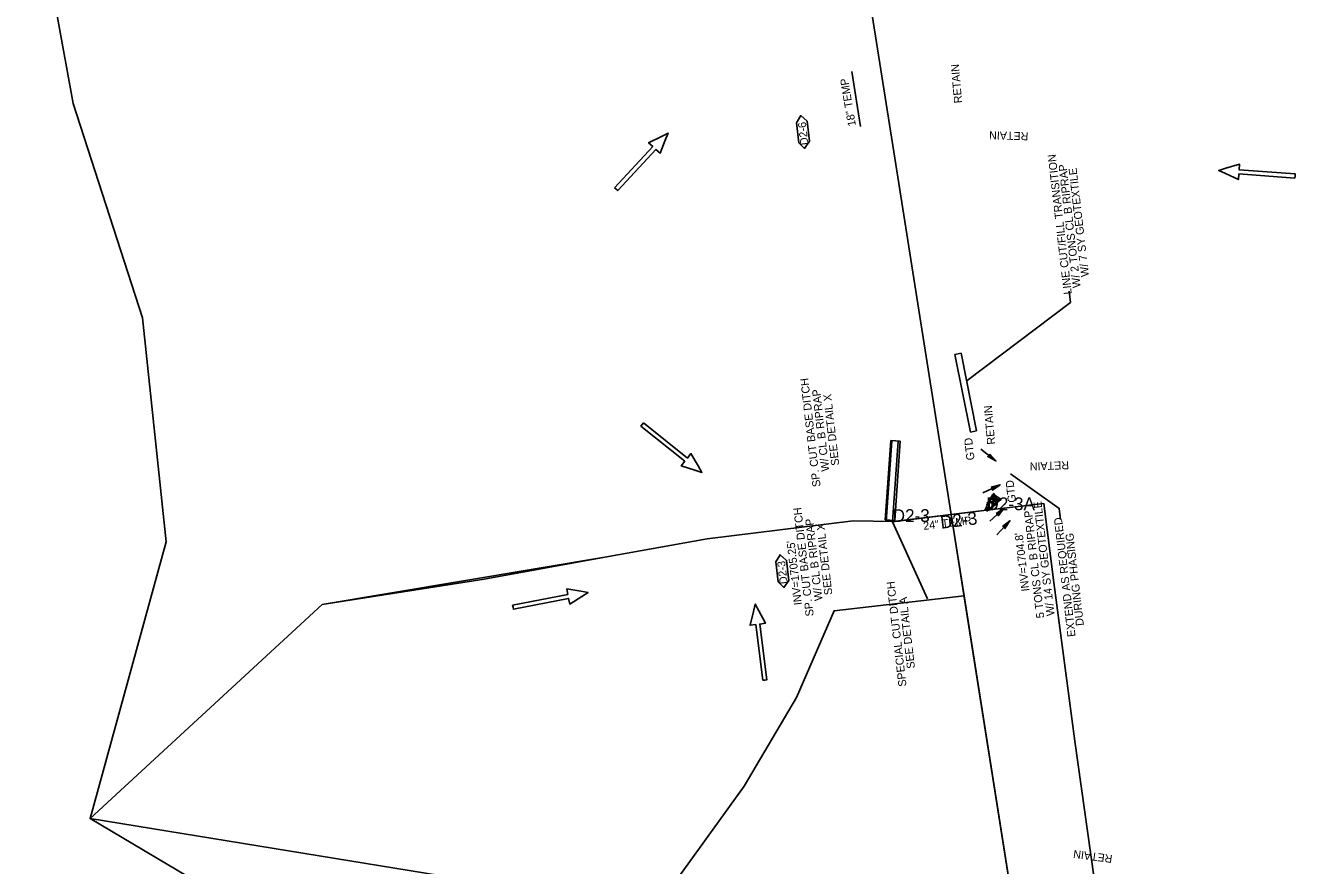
# Model space of a CAD drawing. Extents: x 465700 to 483515, y 488970 to 507540.
# Drawn here: x 477666 to 478460, y 495749 to 496274 of the extents above; entities that cross this region are included whole.
import ezdxf

# ---------------------------------------------------------------- set-up
doc = ezdxf.new("R2010")
doc.units = 0
for name, color, linetype in [('Default', 7, 'Continuous'), ('Exist Plan Preparation Drainage Flow Arrows', 7, 'Continuous'), ('Exist Plan Preparation Watershed Blue', 7, 'Continuous'), ('Prop Drainage Structure Box Number Symbol CELL', 7, 'Continuous'), ('Prop Drainage Structure Pipe Collar Label', 7, 'Continuous'), ('Prop Drainage Structure Pipe RCP 24in Class IV', 7, 'Continuous'), ('Prop Drainage Structure Pipe RCP 24in Class IV Label', 7, 'Continuous'), ('Prop Drainage Structure Pipe Side Drain 18in', 7, 'Continuous'), ('Prop Drainage Structure Pipe Side Drain 18in Label', 7, 'Continuous'), ('Prop Drainage Structure Pipe Stub Out CELL', 7, 'Continuous'), ('Prop Drainage Structure Tops and Inverts LABEL', 7, 'Continuous'), ('Prop Earthen Structure Ditch Flow Line', 7, 'Continuous'), ('Prop Earthen Structure V Ditch Lateral Detail Label', 7, 'Continuous'), ('Prop Erosion Rip Rap Class B', 7, 'Continuous'), ('Prop Erosion Rip Rap Pad at Outlet CELL', 7, 'Continuous'), ('Prop Erosion Rip Rap Pad at Outlet Label', 7, 'Continuous'), ('Prop Plan Preparation Grade to Drain Arrows CELL', 7, 'Continuous'), ('Prop Plan Preparation Grade to Drain Arrows Label', 7, 'Continuous'), ('Scratch_Level_4', 7, 'Continuous'), ('Scratch_Level_8', 7, 'Continuous')]:
    doc.layers.add(name, color=color, linetype=linetype)

# ---------------------------------------------------------------- blocks, each defined once
blk = doc.blocks.new('Existing ground flow arrow')
at = {"layer": 'Default'}
blk.add_line((2.5, -4.33), (2.5, -4.33), dxfattribs=at)
blk.add_lwpolyline([(-1.29, -47.2), (-1.28, -12.53), (-4.77, -12.53), (-1.65, -4.33), (0, 0), (1.65, -4.33), (4.78, -12.53), (1.28, -12.52), (1.29, -47.19), (0, -47.2)], close=True, dxfattribs=at)

msp = doc.modelspace()

# ---------------------------------------------------------------- linework, layer by layer
at = {"layer": 'Exist Plan Preparation Watershed Blue'}
for points in [[(478193.03, 496293.65), (478208.66, 496194.88), (478224.29, 496096.11), (478244.5, 495968.4), (478252.55, 495917.62), (478171.36, 495908.37), (478147.78, 495854.29), (478115.21, 495798.76), (478059.1, 495721.12), (477706.62, 495778.57), (477754.11, 495951.45), (477739.34, 496091.29), (477696.06, 496225.09), (477666.24, 496388.81)], [(478286.82, 495701.03), (478271.18, 495799.8), (478255.55, 495898.57), (478244.5, 495968.4), (478264.82, 495970.97), (478302.44, 495975.33), (478308.68, 495926.08), (478321.83, 495826.95), (478335.71, 495727.91)], [(478059.1, 495721.12), (478115.21, 495798.76), (478147.78, 495854.29), (478171.36, 495908.37), (478252.55, 495917.62), (478301.78, 495606.48)], [(478018.35, 495593.67), (477706.62, 495778.57), (478059.1, 495721.12)]]:
    msp.add_lwpolyline(points, dxfattribs=at)
at = {"layer": 'Prop Drainage Structure Box Number Symbol CELL'}
for points in [[(478149.28, 496200.57), (478147.83, 496213.09), (478150.56, 496217.54), (478154.57, 496214.03), (478156.02, 496201.51), (478152.93, 496197.13), (478149.28, 496200.57)], [(478136.34, 495926.37), (478134.89, 495938.89), (478137.63, 495943.34), (478141.64, 495939.83), (478143.09, 495927.31), (478139.99, 495922.93), (478136.34, 495926.37)]]:
    msp.add_lwpolyline(points, dxfattribs=at)
at = {"layer": 'Prop Drainage Structure Pipe RCP 24in Class IV'}
msp.add_line((478208.45, 495964.09), (478266.49, 495971.16), dxfattribs=at)
at = {"layer": 'Prop Drainage Structure Pipe Side Drain 18in'}
msp.add_line((478187.9, 496210.87), (478182.45, 496245.11), dxfattribs=at)
at = {"layer": 'Prop Drainage Structure Pipe Stub Out CELL'}
msp.add_line((478207.93, 495963.82), (478207.93, 495963.82), dxfattribs=at)
msp.add_line((478207.93, 495963.82), (478207.93, 495963.82), dxfattribs=at)
msp.add_lwpolyline([(478207.93, 495963.84), (478207.95, 495963.83), (478207.94, 495963.81), (478207.92, 495963.82), (478207.93, 495963.84)], dxfattribs=at)
at = {"layer": 'Prop Earthen Structure Ditch Flow Line'}
msp.add_line((478207.32, 496014.49), (478203.94, 495964.11), dxfattribs=at)
for points in [[(478211.31, 496014.22), (478207.93, 495963.85)], [(478229.76, 495915.9), (478207.93, 495963.85)]]:
    msp.add_lwpolyline(points, dxfattribs=at)
at = {"layer": 'Prop Erosion Rip Rap Class B'}
for p, q in [((478250.75, 496069.23), (478246.82, 496068.45)), ((478246.82, 496068.45), (478256.49, 496019.98)), ((478260.41, 496020.76), (478250.75, 496069.23)), ((478256.49, 496019.98), (478260.41, 496020.76)), ((478206.71, 496014.71), (478203.24, 495965.13)), ((478212.69, 496014.29), (478206.71, 496014.71)), ((478209.23, 495964.71), (478212.69, 496014.29)), ((478203.24, 495965.13), (478209.23, 495964.71))]:
    msp.add_line(p, q, dxfattribs=at)
at = {"layer": 'Prop Erosion Rip Rap Pad at Outlet CELL'}
msp.add_line((478266.49, 495971.16), (478266.49, 495971.16), dxfattribs=at)
msp.add_line((478266.49, 495971.16), (478266.49, 495971.16), dxfattribs=at)
for points in [[(478269.53, 495979.7), (478269.87, 495979.73), (478270.28, 495979.54), (478270.4, 495979.24), (478270.23, 495978.99), (478269.7, 495979.27), (478269.49, 495979.5), (478269.53, 495979.7)], [(478270.6, 495979.83), (478270.29, 495979.92), (478270.02, 495980.24), (478270.06, 495980.63), (478270.26, 495980.71), (478270.76, 495980.37), (478270.71, 495979.99), (478270.6, 495979.83)], [(478270.66, 495979.28), (478270.64, 495979.79), (478270.95, 495980.77), (478271.65, 495980.92), (478272.01, 495980.52), (478271.59, 495979.36), (478271.17, 495979.11), (478270.62, 495979.22)], [(478271.23, 495981.53), (478271.32, 495981.24), (478271.12, 495980.78), (478270.81, 495980.72), (478270.68, 495980.86), (478270.83, 495981.43), (478271, 495981.54), (478271.23, 495981.53)], [(478272.86, 495979.12), (478272.52, 495979.27), (478272, 495979.63), (478272.14, 495980.18), (478272.37, 495980.37), (478273.07, 495979.75), (478273.09, 495979.37), (478272.86, 495979.12)], [(478265.76, 495971.87), (478265.99, 495971.81), (478266.56, 495971.69), (478266.5, 495971.36), (478266.4, 495971.2), (478265.8, 495971.33), (478265.59, 495971.62), (478265.76, 495971.87)], [(478266.96, 495972.99), (478266.93, 495972.64), (478266.78, 495972.03), (478266.26, 495971.88), (478265.93, 495972.11), (478266.28, 495972.96), (478266.61, 495973.09), (478266.96, 495972.99)], [(478267.93, 495972.5), (478267.46, 495972.69), (478266.63, 495973.26), (478266.73, 495974.02), (478267.13, 495974.25), (478268.1, 495973.48), (478268.19, 495972.9), (478267.93, 495972.5)], [(478267.38, 495975.22), (478267.47, 495974.94), (478267.28, 495974.48), (478266.97, 495974.41), (478266.84, 495974.55), (478267.01, 495975.12), (478267.17, 495975.24), (478267.38, 495975.22)], [(478268.43, 495971.06), (478267.99, 495971.14), (478267.01, 495971.45), (478266.86, 495972.15), (478267.2, 495972.57), (478268.35, 495972.12), (478268.65, 495971.55), (478268.5, 495971.16)], [(478267.93, 495975.03), (478267.53, 495975.16), (478267.04, 495975.5), (478267.14, 495976.06), (478267.45, 495976.22), (478268.1, 495975.65), (478268.09, 495975.26), (478267.93, 495975.03)], [(478267.93, 495974.99), (478267.98, 495974.68), (478267.76, 495974.25), (478267.48, 495974.16), (478267.3, 495974.29), (478267.51, 495974.92), (478267.71, 495975.01), (478267.93, 495974.99)], [(478268.22, 495974.47), (478268.3, 495974.2), (478268.1, 495973.74), (478267.8, 495973.66), (478267.67, 495973.8), (478267.83, 495974.38), (478268, 495974.49), (478268.22, 495974.47)], [(478268.22, 495976.93), (478268.3, 495976.64), (478268.1, 495976.18), (478267.81, 495976.12), (478267.68, 495976.26), (478267.83, 495976.83), (478268, 495976.93), (478268.22, 495976.93)], [(478267.97, 495977.45), (478268.23, 495977.49), (478268.64, 495977.35), (478268.77, 495977.02), (478268.59, 495976.75), (478268.06, 495977.03), (478267.87, 495977.29), (478267.97, 495977.45)], [(478268.67, 495971.99), (478268.48, 495972.12), (478268.11, 495972.37), (478268.19, 495972.69), (478268.3, 495972.84), (478268.79, 495972.5), (478268.91, 495972.15), (478268.67, 495971.99)], [(478269.8, 495975.86), (478270.1, 495975.06), (478270.13, 495973.32), (478269.08, 495972.72), (478268.29, 495972.98), (478268.19, 495975.14), (478268.85, 495975.87), (478269.78, 495976.03)], [(478269.02, 495976.72), (478269.07, 495976.45), (478268.86, 495976.01), (478268.57, 495975.93), (478268.39, 495976.07), (478268.6, 495976.65), (478268.8, 495976.74), (478269.02, 495976.72)], [(478268.92, 495978.07), (478269.46, 495978.02), (478270.61, 495977.77), (478270.73, 495976.82), (478270.45, 495976.42), (478269.04, 495976.89), (478268.63, 495977.53), (478268.81, 495978.14)], [(478269.39, 495972.72), (478269.47, 495972.45), (478269.28, 495971.98), (478268.97, 495971.93), (478268.82, 495972.04), (478268.98, 495972.65), (478269.19, 495972.77), (478269.39, 495972.72)], [(478269.42, 495979.02), (478269.51, 495978.74), (478269.32, 495978.28), (478269.02, 495978.2), (478268.89, 495978.35), (478269.04, 495978.92), (478269.2, 495979.03), (478269.42, 495979.02)], [(478270.02, 495973.07), (478270.05, 495972.77), (478269.87, 495972.3), (478269.59, 495972.23), (478269.4, 495972.36), (478269.61, 495972.98), (478269.81, 495973.09), (478270.02, 495973.07)], [(478270.1, 495975.81), (478269.79, 495975.88), (478269.51, 495976.21), (478269.55, 495976.6), (478269.75, 495976.68), (478270.24, 495976.34), (478270.21, 495975.96), (478270.1, 495975.81)], [(478270.15, 495978.11), (478269.83, 495978.18), (478269.56, 495978.51), (478269.59, 495978.9), (478269.8, 495978.98), (478270.29, 495978.64), (478270.26, 495978.26), (478270.15, 495978.11)], [(478270.7, 495975.78), (478270.78, 495975.51), (478270.56, 495975.06), (478270.29, 495974.98), (478270.1, 495975.11), (478270.28, 495975.71), (478270.5, 495975.83), (478270.7, 495975.78)], [(478271.27, 495974), (478270.91, 495973.99), (478270.24, 495974.21), (478270.14, 495974.65), (478270.32, 495974.89), (478271.17, 495974.68), (478271.37, 495974.3), (478271.27, 495974)], [(478270.87, 495973.23), (478270.57, 495973.33), (478270.15, 495973.58), (478270.26, 495973.92), (478270.46, 495974.09), (478270.94, 495973.67), (478271, 495973.36), (478270.87, 495973.23)], [(478270.86, 495978.72), (478270.91, 495978.48), (478270.74, 495977.94), (478270.42, 495977.89), (478270.3, 495978.03), (478270.45, 495978.65), (478270.61, 495978.76), (478270.86, 495978.72)], [(478271.9, 495975.14), (478271.41, 495975.35), (478270.63, 495976.01), (478270.73, 495976.68), (478271.17, 495977.01), (478272.1, 495976.24), (478272.25, 495975.53), (478271.9, 495975.14)], [(478270.84, 495975.36), (478271.08, 495975.33), (478271.6, 495975.21), (478271.57, 495974.83), (478271.48, 495974.7), (478270.85, 495974.86), (478270.76, 495975.05), (478270.84, 495975.36)], [(478270.8, 495977.32), (478270.88, 495977.76), (478271.22, 495978.77), (478271.89, 495978.88), (478272.32, 495978.58), (478271.85, 495977.46), (478271.38, 495977.04), (478270.91, 495977.29)], [(478272.02, 495975.02), (478272.09, 495974.75), (478271.91, 495974.28), (478271.6, 495974.23), (478271.44, 495974.34), (478271.6, 495974.95), (478271.82, 495975.07), (478272.02, 495975.02)], [(478272.13, 495979.62), (478272.2, 495979.34), (478272.03, 495978.86), (478271.71, 495978.81), (478271.56, 495978.92), (478271.72, 495979.55), (478271.93, 495979.67), (478272.13, 495979.62)], [(478272.26, 495977.44), (478272.33, 495977.13), (478272.13, 495976.67), (478271.82, 495976.62), (478271.68, 495976.75), (478271.85, 495977.32), (478272.04, 495977.46), (478272.26, 495977.44)], [(478272.23, 495976.5), (478272.44, 495976.44), (478272.91, 495976.24), (478272.96, 495975.94), (478272.88, 495975.81), (478272.35, 495975.9), (478272.17, 495976.17), (478272.19, 495976.39)], [(478272.77, 495975.74), (478272.85, 495975.46), (478272.66, 495975), (478272.35, 495974.95), (478272.2, 495975.06), (478272.35, 495975.67), (478272.57, 495975.79), (478272.77, 495975.74)], [(478272.38, 495978.42), (478272.77, 495978.37), (478273.42, 495978.06), (478273.49, 495977.64), (478273.31, 495977.4), (478272.52, 495977.69), (478272.27, 495977.99), (478272.38, 495978.42)], [(478273.02, 495977.29), (478272.97, 495977.09), (478272.85, 495976.57), (478272.47, 495976.56), (478272.32, 495976.67), (478272.5, 495977.32), (478272.77, 495977.33), (478273.02, 495977.29)], [(478274.24, 495977.67), (478273.77, 495977.9), (478272.95, 495978.43), (478273.07, 495979.21), (478273.53, 495979.48), (478274.47, 495978.74), (478274.53, 495978.1), (478274.24, 495977.67)], [(478273.58, 495976.85), (478273.59, 495976.52), (478273.42, 495976.04), (478273.13, 495976.02), (478272.99, 495976.12), (478273.14, 495976.75), (478273.36, 495976.87), (478273.58, 495976.85)], [(478274.14, 495976.66), (478273.83, 495976.76), (478273.41, 495977), (478273.52, 495977.34), (478273.72, 495977.52), (478274.2, 495977.09), (478274.26, 495976.79), (478274.14, 495976.66)], [(478274.75, 495976.97), (478274.46, 495977.08), (478274.03, 495977.33), (478274.14, 495977.66), (478274.34, 495977.84), (478274.82, 495977.41), (478274.88, 495977.11), (478274.75, 495976.97)], [(478275.21, 495977.88), (478274.91, 495977.98), (478274.49, 495978.23), (478274.6, 495978.57), (478274.8, 495978.74), (478275.28, 495978.32), (478275.34, 495978.02), (478275.21, 495977.88)], [(478266.66, 495971.4), (478266.88, 495971.33), (478267.41, 495971.24), (478267.41, 495970.89), (478267.3, 495970.74), (478266.64, 495970.86), (478266.49, 495971.16), (478266.66, 495971.4)]]:
    msp.add_lwpolyline(points, dxfattribs=at)
at = {"layer": 'Prop Erosion Rip Rap Pad at Outlet Label'}
for points in [[(478254.57, 496052.09), (478319.04, 496100.97), (478318.24, 496107.94)], [(478281.57, 495993.88), (478311.95, 495972.33), (478312.76, 495965.36)]]:
    msp.add_lwpolyline(points, dxfattribs=at)
at = {"layer": 'Prop Plan Preparation Grade to Drain Arrows CELL'}
for p, q in [((478263.02, 496009.32), (478272.46, 496001.92)), ((478264.18, 495981.92), (478275.02, 495987.09)), ((478268.57, 495964.23), (478277.45, 495972.31)), ((478273.09, 495955.72), (478281.2, 495964.56))]:
    msp.add_line(p, q, dxfattribs=at)
for points in [[(478268.55, 496006.19), (478272.46, 496001.92), (478267.38, 496004.69), (478268.53, 496005)], [(478269.45, 495985.49), (478275.02, 495987.09), (478270.27, 495983.77), (478270.5, 495984.94)], [(478272.59, 495969.16), (478277.45, 495972.31), (478273.86, 495967.76), (478273.75, 495968.94)], [(478276.64, 495960.99), (478281.2, 495964.56), (478278.04, 495959.71), (478277.82, 495960.88)]]:
    msp.add_lwpolyline(points, close=True, dxfattribs=at)
at = {"layer": 'Scratch_Level_4'}
msp.add_line((478212.98, 495964.83), (478218.98, 495965.16), dxfattribs=at)
msp.add_lwpolyline([(478193.03, 496293.65), (478208.66, 496194.88), (478224.29, 496096.11), (478244.5, 495968.4), (478208.45, 495964.09), (478183.2, 495964.51), (478092.16, 495953.31), (478028.09, 495941.8), (477952.8, 495928.18), (477851.61, 495912.37), (477706.62, 495778.57), (477754.11, 495951.45), (477739.34, 496091.29), (477696.06, 496225.09), (477666.24, 496388.81)], dxfattribs=at)
msp.add_lwpolyline([(478244.5, 495968.4), (478252.55, 495917.62), (478171.36, 495908.37), (478147.78, 495854.29), (478115.21, 495798.76), (478059.1, 495721.12), (477706.62, 495778.57), (477851.61, 495912.37), (478028.09, 495941.8), (478092.16, 495953.31), (478183.2, 495964.51), (478208.45, 495964.09), (478222.82, 495965.71)], close=True, dxfattribs=at)
at = {"layer": 'Scratch_Level_8'}
msp.add_line((478207.93, 495963.82), (478266.49, 495971.16), dxfattribs=at)

# ---------------------------------------------------------------- block references
at = {"layer": 'Exist Plan Preparation Drainage Flow Arrows'}
for p, xscale, yscale, rotation in [((478067.7, 496206.66), 1.0124070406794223, 1.0124070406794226, -42.81018145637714), ((478411.61, 496183.34), 1.0124070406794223, 1.0124070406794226, 85.8410987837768), ((478088.77, 495994.78), 1.0124070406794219, 1.0124070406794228, -128.8547415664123), ((478017.75, 495919.73), 1.012407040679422, 1.0124070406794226, -79.0354501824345), ((478122.08, 495912.52), 1.012407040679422, 1.0124070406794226, 7.2305024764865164)]:
    msp.add_blockref('Existing ground flow arrow', p, dxfattribs=dict(at, xscale=xscale, yscale=yscale, rotation=rotation))

# ---------------------------------------------------------------- texts
at = {"layer": 'Prop Drainage Structure Box Number Symbol CELL'}
for s, p in [('D2-6', (478155.34, 496199.42)), ('D2-3', (478142.39, 495925.31))]:
    msp.add_text(s, height=5, rotation=96.60448, dxfattribs=at).set_placement(p)
at = {"layer": 'Prop Drainage Structure Pipe Collar Label'}
for rotation, p in [(95.04776, (478251.36, 496225.51)), (178.52434, (478292.76, 496207.16)), (95.04776, (478272.01, 496012.37)), (182.0532, (478318, 496001.82)), (172.54326, (478345.43, 495755.84))]:
    msp.add_text('RETAIN', height=5, rotation=rotation, dxfattribs=at).set_placement(p)
at = {"layer": 'Prop Drainage Structure Pipe RCP 24in Class IV Label'}
msp.add_text('24" TEMP', height=5, rotation=6.9453, dxfattribs=at).set_placement((478227.39, 495958.84))
at = {"layer": 'Prop Drainage Structure Pipe Side Drain 18in Label'}
msp.add_text('18" TEMP', height=5, rotation=99.58679, dxfattribs=at).set_placement((478185.03, 496211.38))
at = {"layer": 'Prop Drainage Structure Pipe Stub Out CELL'}
msp.add_text('SO', height=0.0104, rotation=278.99254, dxfattribs=at).set_placement((478207.93, 495963.83))
at = {"layer": 'Prop Drainage Structure Tops and Inverts LABEL'}
for s, p in [("INV=1704.8'", (478293.33, 495920.79)), ("INV=1705.25'", (478151.3, 495912.2))]:
    msp.add_text(s, height=5, rotation=96.60736, dxfattribs=at).set_placement(p)
at = {"layer": 'Prop Earthen Structure V Ditch Lateral Detail Label'}
for s, p in [('SP. CUT BASE DITCH', (478162.95, 495986)), ('W/ CL B RIPRAP ', (478168.44, 495995.67)), ('SEE DETAIL X', (478174.62, 495999.29)), ('SP. CUT BASE DITCH', (478158.65, 495905.21)), ('W/ CL B RIPRAP ', (478164.14, 495914.88)), ('SEE DETAIL X', (478170.32, 495918.51)), ('SPECIAL CUT DITCH', (478216.6, 495861.31)), ('SEE DETAIL A', (478221.91, 495872.54))]:
    msp.add_text(s, height=5, rotation=96.56577, dxfattribs=at).set_placement(p)
at = {"layer": 'Prop Erosion Rip Rap Pad at Outlet Label'}
for s, rotation, p in [('LINE CUT/FILL TRANSITION ', 96.59296, (478319.82, 496106.21)), ('W/ 2 TONS CL B RIPRAP', 96.59296, (478325.39, 496110.33)), ('W/ 7 SY GEOTEXTILE', 96.59296, (478330.63, 496117.2)), ('W/ 14 SY GEOTEXTILE', 96.60736, (478309.12, 495905.47)), ('5 TONS CL B RIPRAP', 96.60736, (478302.69, 495904.05)), ('EXTEND AS REQUIRED', 96.59296, (478322.2, 495892.35)), ('DURING PHASING', 96.59296, (478327.44, 495899.24))]:
    msp.add_text(s, height=5, rotation=rotation, dxfattribs=at).set_placement(p)
at = {"layer": 'Prop Plan Preparation Grade to Drain Arrows Label'}
for p in [(478259.12, 496002.63), (478285.01, 495976.19)]:
    msp.add_text('GTD', height=5, rotation=96.60736, dxfattribs=at).set_placement(p)
at = {"layer": 'Scratch_Level_8'}
for s, p in [('D2-3', (478207.93, 495963.82)), ('D2-3A', (478266.49, 495971.16))]:
    msp.add_text(s, height=8, dxfattribs=at).set_placement(p)
msp.add_text('D2-3', height=8, rotation=7.13892, dxfattribs=at).set_placement((478238.2, 495959.55))

doc.saveas('drawing.dxf')
